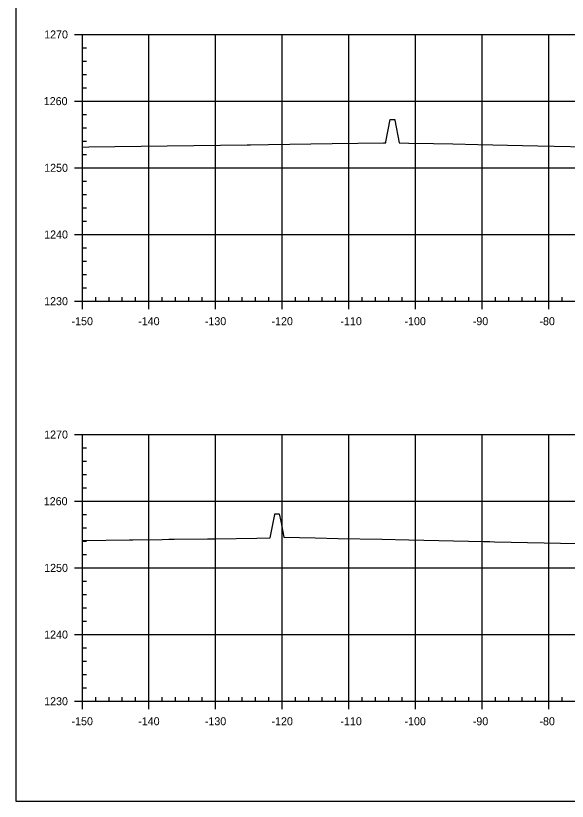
# Model space of a CAD drawing. Extents: x 659657 to 668193, y 633084 to 648639.
# Drawn here: x 667152.5 to 667235.3, y 643502.4 to 643620.2 of the extents above; entities that cross this region are included whole.
import ezdxf

# ---------------------------------------------------------------- set-up
doc = ezdxf.new("R2010")
doc.units = 0
for name, color, linetype in [('R_Axis', 7, 'Continuous'), ('R_Axis Annot', 7, 'Continuous'), ('R_Exist Surface', 7, 'Continuous'), ('R_Grid', 7, 'Continuous'), ('T_SIGNAL CONTROL CABINET', 7, 'Continuous')]:
    doc.layers.add(name, color=color, linetype=linetype)

msp = doc.modelspace()

# ---------------------------------------------------------------- linework, layer by layer
at = {"layer": 'R_Axis'}
for p, q in [((667161.31, 643617.39), (667163.71, 643617.39)), ((667162.51, 643577.39), (667162.51, 643617.39)), ((667162.51, 643615.39), (667163.11, 643615.39)), ((667162.51, 643613.39), (667163.11, 643613.39)), ((667162.51, 643611.39), (667163.11, 643611.39)), ((667162.51, 643609.39), (667163.11, 643609.39)), ((667161.31, 643607.39), (667163.71, 643607.39)), ((667162.51, 643605.39), (667163.11, 643605.39)), ((667162.51, 643603.39), (667163.11, 643603.39)), ((667162.51, 643601.39), (667163.11, 643601.39)), ((667162.51, 643599.39), (667163.11, 643599.39)), ((667161.31, 643597.39), (667163.71, 643597.39)), ((667162.51, 643595.39), (667163.11, 643595.39)), ((667162.51, 643593.39), (667163.11, 643593.39)), ((667162.51, 643591.39), (667163.11, 643591.39)), ((667162.51, 643589.39), (667163.11, 643589.39)), ((667161.31, 643587.39), (667163.71, 643587.39)), ((667162.51, 643585.39), (667163.11, 643585.39)), ((667162.51, 643583.39), (667163.11, 643583.39)), ((667162.51, 643581.39), (667163.11, 643581.39)), ((667162.51, 643579.39), (667163.11, 643579.39)), ((667162.51, 643576.19), (667162.51, 643578.59)), ((667164.51, 643577.39), (667164.51, 643577.99)), ((667166.51, 643577.39), (667166.51, 643577.99)), ((667168.51, 643577.39), (667168.51, 643577.99)), ((667170.51, 643577.39), (667170.51, 643577.99)), ((667172.51, 643576.19), (667172.51, 643578.59)), ((667174.51, 643577.39), (667174.51, 643577.99)), ((667176.51, 643577.39), (667176.51, 643577.99)), ((667178.51, 643577.39), (667178.51, 643577.99)), ((667180.51, 643577.39), (667180.51, 643577.99)), ((667182.51, 643576.19), (667182.51, 643578.59)), ((667184.51, 643577.39), (667184.51, 643577.99)), ((667186.51, 643577.39), (667186.51, 643577.99)), ((667188.51, 643577.39), (667188.51, 643577.99)), ((667190.51, 643577.39), (667190.51, 643577.99)), ((667192.51, 643576.19), (667192.51, 643578.59)), ((667194.51, 643577.39), (667194.51, 643577.99)), ((667196.51, 643577.39), (667196.51, 643577.99)), ((667198.51, 643577.39), (667198.51, 643577.99)), ((667200.51, 643577.39), (667200.51, 643577.99)), ((667202.51, 643576.19), (667202.51, 643578.59)), ((667204.51, 643577.39), (667204.51, 643577.99)), ((667206.51, 643577.39), (667206.51, 643577.99)), ((667208.51, 643577.39), (667208.51, 643577.99)), ((667210.51, 643577.39), (667210.51, 643577.99)), ((667212.51, 643576.19), (667212.51, 643578.59)), ((667214.51, 643577.39), (667214.51, 643577.99)), ((667216.51, 643577.39), (667216.51, 643577.99)), ((667218.51, 643577.39), (667218.51, 643577.99)), ((667220.51, 643577.39), (667220.51, 643577.99)), ((667222.51, 643576.19), (667222.51, 643578.59)), ((667224.51, 643577.39), (667224.51, 643577.99)), ((667226.51, 643577.39), (667226.51, 643577.99)), ((667228.51, 643577.39), (667228.51, 643577.99)), ((667230.51, 643577.39), (667230.51, 643577.99)), ((667232.51, 643576.19), (667232.51, 643578.59)), ((667234.51, 643577.39), (667234.51, 643577.99)), ((667161.31, 643577.39), (667163.71, 643577.39)), ((667162.51, 643577.39), (667462.51, 643577.39)), ((667161.31, 643557.39), (667163.71, 643557.39)), ((667162.51, 643517.39), (667162.51, 643557.39)), ((667162.51, 643555.39), (667163.11, 643555.39)), ((667162.51, 643553.39), (667163.11, 643553.39)), ((667162.51, 643551.39), (667163.11, 643551.39)), ((667162.51, 643549.39), (667163.11, 643549.39)), ((667161.31, 643547.39), (667163.71, 643547.39)), ((667162.51, 643545.39), (667163.11, 643545.39)), ((667162.51, 643543.39), (667163.11, 643543.39)), ((667162.51, 643541.39), (667163.11, 643541.39)), ((667162.51, 643539.39), (667163.11, 643539.39)), ((667161.31, 643537.39), (667163.71, 643537.39)), ((667162.51, 643535.39), (667163.11, 643535.39)), ((667162.51, 643533.39), (667163.11, 643533.39)), ((667162.51, 643531.39), (667163.11, 643531.39)), ((667162.51, 643529.39), (667163.11, 643529.39)), ((667161.31, 643527.39), (667163.71, 643527.39)), ((667162.51, 643525.39), (667163.11, 643525.39)), ((667162.51, 643523.39), (667163.11, 643523.39)), ((667162.51, 643521.39), (667163.11, 643521.39)), ((667162.51, 643519.39), (667163.11, 643519.39)), ((667162.51, 643516.19), (667162.51, 643518.59)), ((667164.51, 643517.39), (667164.51, 643517.99)), ((667166.51, 643517.39), (667166.51, 643517.99)), ((667168.51, 643517.39), (667168.51, 643517.99)), ((667170.51, 643517.39), (667170.51, 643517.99)), ((667172.51, 643516.19), (667172.51, 643518.59)), ((667174.51, 643517.39), (667174.51, 643517.99)), ((667176.51, 643517.39), (667176.51, 643517.99)), ((667178.51, 643517.39), (667178.51, 643517.99)), ((667180.51, 643517.39), (667180.51, 643517.99)), ((667182.51, 643516.19), (667182.51, 643518.59)), ((667184.51, 643517.39), (667184.51, 643517.99)), ((667186.51, 643517.39), (667186.51, 643517.99)), ((667188.51, 643517.39), (667188.51, 643517.99)), ((667190.51, 643517.39), (667190.51, 643517.99)), ((667192.51, 643516.19), (667192.51, 643518.59)), ((667194.51, 643517.39), (667194.51, 643517.99)), ((667196.51, 643517.39), (667196.51, 643517.99)), ((667198.51, 643517.39), (667198.51, 643517.99)), ((667200.51, 643517.39), (667200.51, 643517.99)), ((667202.51, 643516.19), (667202.51, 643518.59)), ((667204.51, 643517.39), (667204.51, 643517.99)), ((667206.51, 643517.39), (667206.51, 643517.99)), ((667208.51, 643517.39), (667208.51, 643517.99)), ((667210.51, 643517.39), (667210.51, 643517.99)), ((667212.51, 643516.19), (667212.51, 643518.59)), ((667214.51, 643517.39), (667214.51, 643517.99)), ((667216.51, 643517.39), (667216.51, 643517.99)), ((667218.51, 643517.39), (667218.51, 643517.99)), ((667220.51, 643517.39), (667220.51, 643517.99)), ((667222.51, 643516.19), (667222.51, 643518.59)), ((667224.51, 643517.39), (667224.51, 643517.99)), ((667226.51, 643517.39), (667226.51, 643517.99)), ((667228.51, 643517.39), (667228.51, 643517.99)), ((667230.51, 643517.39), (667230.51, 643517.99)), ((667232.51, 643516.19), (667232.51, 643518.59)), ((667234.51, 643517.39), (667234.51, 643517.99)), ((667161.31, 643517.39), (667163.71, 643517.39)), ((667162.51, 643517.39), (667462.51, 643517.39))]:
    msp.add_line(p, q, dxfattribs=at)
at = {"layer": 'R_Exist Surface'}
for points in [[(667162.51, 643600.5), (667163.49, 643600.54), (667175.24, 643600.7), (667187.22, 643600.85), (667187.34, 643600.85), (667187.72, 643600.86), (667190.45, 643600.9), (667200, 643601.04), (667207.72, 643601.16), (667208.05, 643601.16), (667208.07, 643601.29), (667208.72, 643604.66), (667208.72, 643604.66), (667208.72, 643604.66), (667209.37, 643604.66), (667209.39, 643604.66), (667209.39, 643604.64), (667209.39, 643604.64), (667209.4, 643604.56), (667210.06, 643601.14), (667211.52, 643601.11), (667215.22, 643601.03), (667218.11, 643600.97), (667221.83, 643600.9), (667228.55, 643600.76), (667230.83, 643600.71), (667240.61, 643600.51)], [(667162.51, 643541.52), (667169.57, 643541.6), (667169.97, 643541.6), (667170.08, 643541.6), (667174.49, 643541.66), (667175.5, 643541.68), (667176.27, 643541.69), (667181.29, 643541.76), (667182.53, 643541.77), (667188.68, 643541.86), (667190.69, 643541.89), (667190.89, 643542.9), (667191.37, 643545.38), (667191.37, 643545.47), (667191.37, 643545.5), (667191.84, 643545.5), (667192.05, 643545.5), (667192.05, 643545.5), (667192.05, 643545.5), (667192.27, 643544.39), (667192.73, 643542), (667197.46, 643541.9), (667200.9, 643541.82), (667207.46, 643541.68), (667211.48, 643541.59), (667222.71, 643541.35), (667223.64, 643541.33), (667224.36, 643541.31), (667246.68, 643540.84)]]:
    msp.add_lwpolyline(points, dxfattribs=at)
at = {"layer": 'R_Grid'}
for p, q in [((667162.51, 643617.39), (667462.51, 643617.39)), ((667162.51, 643577.39), (667162.51, 643617.39)), ((667172.51, 643577.39), (667172.51, 643617.39)), ((667182.51, 643577.39), (667182.51, 643617.39)), ((667192.51, 643577.39), (667192.51, 643617.39)), ((667202.51, 643577.39), (667202.51, 643617.39)), ((667212.51, 643577.39), (667212.51, 643617.39)), ((667222.51, 643577.39), (667222.51, 643617.39)), ((667232.51, 643577.39), (667232.51, 643617.39)), ((667162.51, 643607.39), (667462.51, 643607.39)), ((667162.51, 643597.39), (667462.51, 643597.39)), ((667162.51, 643587.39), (667462.51, 643587.39)), ((667162.51, 643577.39), (667462.51, 643577.39)), ((667162.51, 643557.39), (667462.51, 643557.39)), ((667162.51, 643517.39), (667162.51, 643557.39)), ((667172.51, 643517.39), (667172.51, 643557.39)), ((667182.51, 643517.39), (667182.51, 643557.39)), ((667192.51, 643517.39), (667192.51, 643557.39)), ((667202.51, 643517.39), (667202.51, 643557.39)), ((667212.51, 643517.39), (667212.51, 643557.39)), ((667222.51, 643517.39), (667222.51, 643557.39)), ((667232.51, 643517.39), (667232.51, 643557.39)), ((667162.51, 643547.39), (667462.51, 643547.39)), ((667162.51, 643537.39), (667462.51, 643537.39)), ((667162.51, 643527.39), (667462.51, 643527.39)), ((667162.51, 643517.39), (667462.51, 643517.39))]:
    msp.add_line(p, q, dxfattribs=at)
at = {"layer": 'T_SIGNAL CONTROL CABINET'}
msp.add_lwpolyline([(667152.51, 643502.39), (667492.51, 643502.39), (667492.51, 643722.39), (667152.51, 643722.39)], close=True, dxfattribs=at)

# ---------------------------------------------------------------- texts
at = {"layer": 'R_Axis Annot'}
for s, p in [('1270', (667156.78, 643616.79)), ('1260', (667156.72, 643606.79)), ('1250', (667156.78, 643596.79)), ('1240', (667156.78, 643586.79)), ('1230', (667156.78, 643576.79)), ('-150', (667160.89, 643573.79)), ('-140', (667170.89, 643573.79)), ('-130', (667180.89, 643573.79)), ('-120', (667190.89, 643573.79)), ('-110', (667201.23, 643573.79)), ('-100', (667210.84, 643573.79)), ('-90', (667221.09, 643573.79)), ('-80', (667231.09, 643573.79)), ('1270', (667156.78, 643556.79)), ('1260', (667156.72, 643546.79)), ('1250', (667156.78, 643536.79)), ('1240', (667156.78, 643526.79)), ('1230', (667156.78, 643516.79)), ('-150', (667160.89, 643513.79)), ('-140', (667170.89, 643513.79)), ('-130', (667180.89, 643513.79)), ('-120', (667190.89, 643513.79)), ('-110', (667201.23, 643513.79)), ('-100', (667210.84, 643513.79)), ('-90', (667221.09, 643513.79)), ('-80', (667231.09, 643513.79))]:
    msp.add_text(s, height=1.2, dxfattribs=at).set_placement(p)

doc.saveas('drawing.dxf')
